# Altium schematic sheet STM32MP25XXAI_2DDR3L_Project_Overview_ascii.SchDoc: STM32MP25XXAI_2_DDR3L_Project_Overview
size A4; Date: Not used; ApprovedBy: Not used; CheckedBy: Not used; Author: Not used; CompanyName: STMicroelectronics; DrawnBy: Not used; Engineer: Not used; Organization: Not used; Address1: Not used; Address2: Not used; Address3: Not used; Address4: Not used; DocumentNumber: 1; Revision: Not used; SheetNumber: 1; SheetTotal: 7
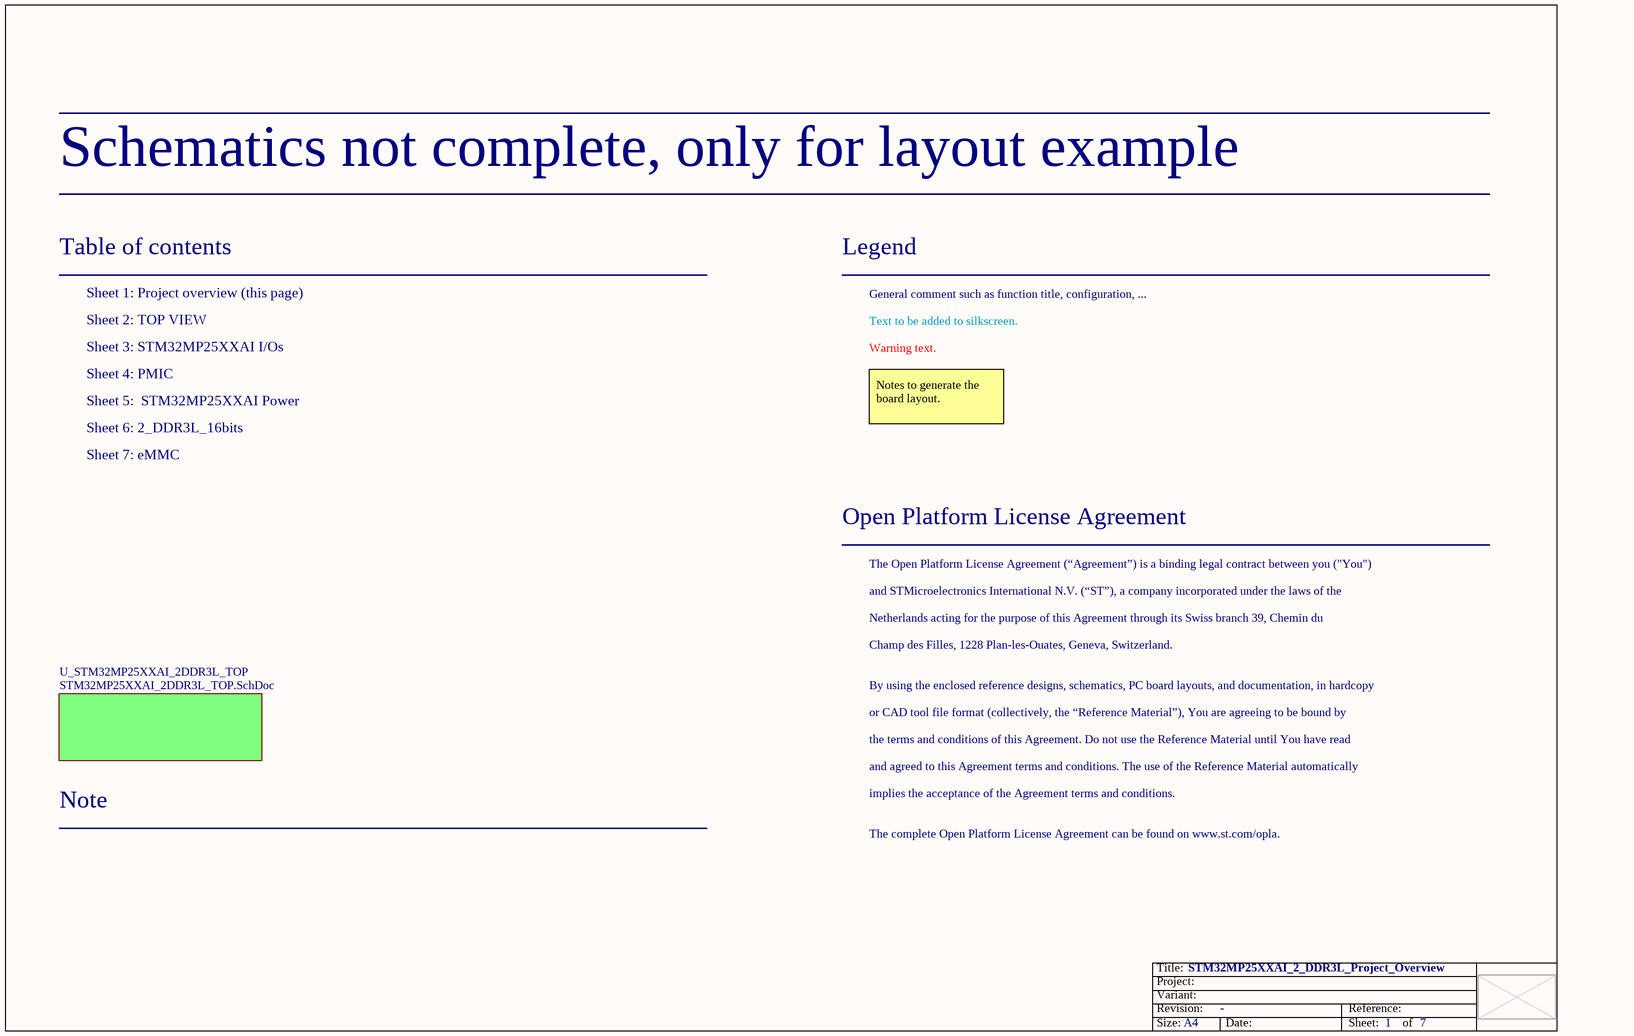
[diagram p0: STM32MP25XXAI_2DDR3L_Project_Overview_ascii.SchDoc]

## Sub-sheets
U_STM32MP25XXAI_2DDR3L_TOP = STM32MP25XXAI_2DDR3L_TOP.SchDoc: no entries

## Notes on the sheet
- Schematics not complete, only for layout example
- Table of contents
- Sheet 1: Project overview (this page)
- Legend
- General comment such as function title, configuration, ...
- Sheet 2: TOP VIEW
- Sheet 3: STM32MP25XXAI I/Os
- Sheet 4: PMIC
- Text to be added to silkscreen.
- Warning text.
- Sheet 5:  STM32MP25XXAI Power
- Sheet 6: 2_DDR3L_16bits
- Notes to generate the board layout.
- Sheet 7: eMMC
- Open Platform License Agreement
- The Open Platform License Agreement (“Agreement”) is a binding legal contract between you ("You")
- and STMicroelectronics International N.V. (“ST”), a company incorporated under the laws of the
- Netherlands acting for the purpose of this Agreement through its Swiss branch 39, Chemin du
- Champ des Filles, 1228 Plan-les-Ouates, Geneva, Switzerland.
- By using the enclosed reference designs, schematics, PC board layouts, and documentation, in hardcopy
- or CAD tool file format (collectively, the “Reference Material”), You are agreeing to be bound by
- the terms and conditions of this Agreement. Do not use the Reference Material until You have read
- and agreed to this Agreement terms and conditions. The use of the Reference Material automatically
- Note
- implies the acceptance of the Agreement terms and conditions.
- The complete Open Platform License Agreement can be found on www.st.com/opla.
